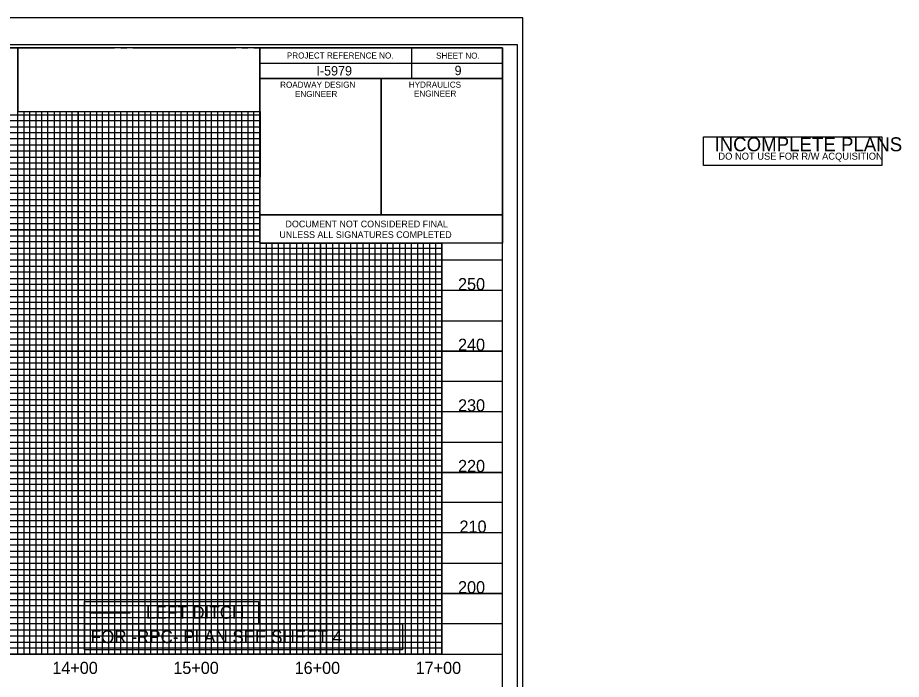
# Model space of a CAD drawing. Extents: x 1810963 to 1812960, y 722070 to 723170.
# Drawn here: x 1812230 to 1812960, y 722624 to 723170 of the extents above; entities that cross this region are included whole.
import ezdxf

# ---------------------------------------------------------------- set-up
doc = ezdxf.new("R2010")
doc.units = 0
for name, color, linetype in [('Exist Horizontal Alignment Tick Label', 7, 'Continuous'), ('Old_Level_11', 7, 'Continuous'), ('Old_Level_2', 7, 'Continuous'), ('Prop Conc 2ft 6in Curb and Gutter', 7, 'Continuous'), ('Prop Dimension Text', 7, 'Continuous'), ('Prop Grid Mask', 7, 'Continuous'), ('Prop Horizontal Alignment Station Label', 7, 'Continuous'), ('Prop RDY Traffic Signal CELL', 7, 'Continuous'), ('Prop Shade Heavy', 7, 'Continuous'), ('Prop Shade Light', 7, 'Continuous'), ('Prop Vertical Profile Ditch Grade Left', 7, 'Continuous'), ('Scratch_Level_0', 7, 'Continuous'), ('Scratch_Level_3', 7, 'Continuous'), ('Sheet Block Title CELL', 7, 'Continuous'), ('Sheet Layout Profile Border Port 1', 7, 'Continuous'), ('Sheet North Arrow CELL', 7, 'Continuous'), ('Sheet Symbology CELL', 7, 'Continuous'), ('Sheet Title CELL', 7, 'Continuous')]:
    doc.layers.add(name, color=color, linetype=linetype)

msp = doc.modelspace()

# ---------------------------------------------------------------- linework, layer by layer
at = {"layer": 'Old_Level_11'}
msp.add_lwpolyline([(1810976.46, 722092.33), (1812642.96, 722092.33), (1812642.96, 723147.43), (1810976.46, 723147.43)], close=True, dxfattribs=at)
at = {"layer": 'Old_Level_2'}
for points in [[(1812285.68, 722688.37), (1812429.34, 722688.37), (1812429.34, 722669.88), (1812285.68, 722669.88)], [(1812285.68, 722669.88), (1812547.95, 722669.88), (1812547.95, 722648.36), (1812285.68, 722648.36)]]:
    msp.add_lwpolyline(points, close=True, dxfattribs=at)
at = {"layer": 'Prop Conc 2ft 6in Curb and Gutter'}
for p, q in [((1812230.46, 722644.88), (1812230.46, 723144.88)), ((1812280.46, 722644.88), (1812280.46, 723092.45)), ((1812330.46, 722644.88), (1812330.46, 723092.45)), ((1812380.46, 722644.88), (1812380.46, 723092.45)), ((1812430.41, 723044.88), (1811130.46, 723044.88)), ((1812430.46, 722644.88), (1812430.46, 723007.33)), ((1812430.46, 722994.88), (1811130.46, 722994.88)), ((1812480.46, 722644.88), (1812480.46, 722983.83)), ((1812530.46, 722644.88), (1812530.46, 722983.83)), ((1812580.46, 722644.88), (1812580.46, 722983.83)), ((1812630.46, 722944.88), (1811130.46, 722944.88)), ((1812630.46, 722894.88), (1811130.46, 722894.88)), ((1812630.46, 722844.88), (1811130.46, 722844.88)), ((1812630.46, 722794.88), (1811130.46, 722794.88)), ((1812630.46, 722744.88), (1811130.46, 722744.88)), ((1812630.46, 722694.88), (1811130.46, 722694.88))]:
    msp.add_line(p, q, dxfattribs=at)
at = {"layer": 'Prop Dimension Text'}
for p, q in [((1812430.41, 722983.83), (1812430.41, 723007.33)), ((1812430.41, 723007.33), (1812630.45, 723007.33)), ((1812430.41, 722983.83), (1812430.41, 723007.33)), ((1812430.41, 723007.33), (1812630.45, 723007.33)), ((1812630.45, 723007.32), (1812630.45, 722983.82)), ((1812630.45, 723007.32), (1812630.45, 722983.82)), ((1812630.45, 722983.83), (1812430.41, 722983.83)), ((1812630.45, 722983.83), (1812430.41, 722983.83))]:
    msp.add_line(p, q, dxfattribs=at)
at = {"layer": 'Prop Horizontal Alignment Station Label'}
msp.add_lwpolyline([(1812796.56, 723048.01), (1812796.56, 723071.51), (1812943.56, 723071.51), (1812943.56, 723048.01)], close=True, dxfattribs=at)
at = {"layer": 'Prop RDY Traffic Signal CELL'}
msp.add_line((1812647.46, 723169.88), (1810963.46, 723169.88), dxfattribs=at)
at = {"layer": 'Prop Shade Heavy'}
for points in [[(1812180.46, 722644.88), (1812230.46, 722644.88), (1812230.46, 723144.88), (1812280.46, 723144.88)], [(1812330.46, 723144.88), (1812380.46, 723144.88)], [(1812380.46, 723092.45), (1812380.46, 722644.88), (1812430.46, 722644.88), (1812430.46, 723144.88), (1812456.76, 723144.88)], [(1812280.46, 723092.45), (1812280.46, 722644.88), (1812330.46, 722644.88), (1812330.46, 723092.45)], [(1812430.46, 723044.88), (1811130.46, 723044.88), (1811130.46, 722994.88), (1812430.46, 722994.88)], [(1812580.46, 722983.83), (1812580.46, 722644.88), (1812630.46, 722644.88), (1812630.46, 722994.88)], [(1812480.46, 722983.83), (1812480.46, 722644.88), (1812530.46, 722644.88), (1812530.46, 722644.88), (1812530.46, 722983.83)], [(1812630.46, 722944.88), (1811130.46, 722944.88), (1811130.46, 722894.88), (1812630.46, 722894.88)], [(1812630.46, 722844.88), (1811130.46, 722844.88), (1811130.46, 722794.88), (1812630.46, 722794.88)], [(1812630.46, 722744.88), (1811130.46, 722744.88), (1811130.46, 722744.88), (1811130.46, 722694.88), (1812630.46, 722694.88)]]:
    msp.add_lwpolyline(points, dxfattribs=at)
at = {"layer": 'Prop Shade Light'}
for p, q in [((1812255.46, 723144.88), (1812305.46, 723144.88)), ((1812355.46, 723144.88), (1812405.46, 723144.88)), ((1812255.46, 722644.88), (1812255.46, 723092.45)), ((1812305.46, 723092.45), (1812305.46, 722644.88)), ((1812355.46, 722644.88), (1812355.46, 723092.45)), ((1812405.46, 723092.45), (1812405.46, 722644.88)), ((1812455.46, 722644.88), (1812455.46, 722983.83)), ((1812205.46, 722644.88), (1812255.46, 722644.88)), ((1812305.46, 722644.88), (1812355.46, 722644.88)), ((1812405.46, 722644.88), (1812455.46, 722644.88))]:
    msp.add_line(p, q, dxfattribs=at)
for points in [[(1812430.46, 723069.88), (1811130.46, 723069.88), (1811130.46, 723019.88), (1812430.46, 723019.88)], [(1812455.46, 722907.68), (1812455.46, 722644.88), (1812505.46, 722644.88), (1812505.46, 722983.83)], [(1812505.46, 722907.68), (1812505.46, 722644.88), (1812555.46, 722644.88), (1812555.46, 722983.83)], [(1812630.46, 722969.88), (1811130.46, 722969.88), (1811130.46, 722919.88), (1812455.46, 722919.88)], [(1812455.46, 722919.88), (1812630.46, 722919.88)], [(1812630.46, 722869.88), (1811130.46, 722869.88), (1811130.46, 722819.88), (1812630.46, 722819.88)], [(1812630.46, 722769.88), (1811130.46, 722769.88), (1811130.46, 722719.88), (1812630.46, 722719.88)], [(1812630.46, 722669.88), (1811130.46, 722669.88)]]:
    msp.add_lwpolyline(points, dxfattribs=at)
at = {"layer": 'Prop Vertical Profile Ditch Grade Left'}
msp.add_line((1812289.59, 722679.06), (1812323.23, 722679.06), dxfattribs=at)
at = {"layer": 'Scratch_Level_3'}
msp.add_lwpolyline([(1811180.46, 723144.88), (1812230.46, 723144.88), (1812230.46, 723092.45), (1812430.5, 723092.45), (1812430.41, 722983.83), (1812580.46, 722983.83), (1812580.46, 722644.88), (1811180.46, 722644.88)], close=True, dxfattribs=at)
at = {"layer": 'Sheet Layout Profile Border Port 1'}
msp.add_lwpolyline([(1811180.46, 722983.83), (1811180.46, 722644.88), (1812580.46, 722644.88), (1812580.46, 722983.83)], dxfattribs=at)
at = {"layer": 'Sheet North Arrow CELL'}
msp.add_lwpolyline([(1810963.46, 722069.88), (1812647.46, 722069.88), (1812647.46, 723169.88), (1810963.46, 723169.88)], close=True, dxfattribs=at)
at = {"layer": 'Sheet Symbology CELL'}
for p, q in [((1812555.46, 723144.83), (1812555.46, 723119.83)), ((1812430.41, 723132.33), (1812630.46, 723132.33)), ((1812530.46, 723119.83), (1812530.46, 723007.38)), ((1811130.46, 722644.88), (1812630.46, 722644.88))]:
    msp.add_line(p, q, dxfattribs=at)
for points in [[(1812630.46, 723144.88), (1811130.46, 723144.88), (1811130.46, 722094.88), (1812630.46, 722094.88)], [(1812430.41, 723144.88), (1812630.46, 723144.88), (1812630.46, 723119.83), (1812430.41, 723119.83)], [(1812430.41, 723119.83), (1812530.46, 723119.83), (1812530.46, 723007.33), (1812430.41, 723007.33)], [(1812530.46, 723119.83), (1812630.46, 723119.83), (1812630.46, 723007.33), (1812530.46, 723007.33)]]:
    msp.add_lwpolyline(points, close=True, dxfattribs=at)
at = {"layer": 'Sheet Title CELL'}
for p, q in [((1812225.46, 723144.88), (1812235.46, 723144.88)), ((1812240.46, 723144.88), (1812245.46, 723144.88)), ((1812250.46, 723144.88), (1812260.46, 723144.88)), ((1812265.46, 723144.88), (1812270.46, 723144.88)), ((1812275.46, 723144.88), (1812285.46, 723144.88)), ((1812290.46, 723144.88), (1812295.46, 723144.88)), ((1812300.46, 723144.88), (1812310.46, 723144.88)), ((1812315.46, 723144.88), (1812320.46, 723144.88)), ((1811180.46, 723089.88), (1812430.46, 723089.88)), ((1812235.46, 723092.45), (1812235.46, 722644.88)), ((1812240.46, 722644.88), (1812240.46, 723092.45)), ((1812245.46, 723092.45), (1812245.46, 722644.88)), ((1812250.46, 722644.88), (1812250.46, 723092.45)), ((1812260.46, 723092.45), (1812260.46, 722644.88)), ((1812265.46, 722644.88), (1812265.46, 723092.45)), ((1812270.46, 723092.45), (1812270.46, 722644.88)), ((1812275.46, 722644.88), (1812275.46, 723092.45)), ((1812285.46, 723092.45), (1812285.46, 722644.88)), ((1812290.46, 722644.88), (1812290.46, 723092.45)), ((1812295.46, 723092.45), (1812295.46, 722644.88)), ((1812300.46, 722644.88), (1812300.46, 723092.45)), ((1812310.46, 723092.45), (1812310.46, 722644.88)), ((1812315.46, 722644.88), (1812315.46, 723092.45)), ((1812320.46, 723092.45), (1812320.46, 722644.88)), ((1812430.41, 723009.88), (1811180.46, 723009.88)), ((1812430.46, 723004.88), (1811180.46, 723004.88)), ((1812430.46, 722999.88), (1811180.46, 722999.88)), ((1811180.46, 722989.88), (1812430.46, 722989.88)), ((1812430.46, 722984.88), (1811180.46, 722984.88)), ((1811180.46, 722979.88), (1812580.46, 722979.88)), ((1812580.46, 722959.88), (1811180.46, 722959.88)), ((1811180.46, 722954.88), (1812580.46, 722954.88)), ((1812580.46, 722934.88), (1811180.46, 722934.88)), ((1811180.46, 722929.88), (1812580.46, 722929.88)), ((1812580.46, 722909.88), (1811180.46, 722909.88)), ((1811180.46, 722904.88), (1812580.46, 722904.88)), ((1812580.46, 722899.88), (1811180.46, 722899.88)), ((1811180.46, 722889.88), (1812580.46, 722889.88)), ((1812580.46, 722884.88), (1811180.46, 722884.88)), ((1811180.46, 722879.88), (1812580.46, 722879.88)), ((1812580.46, 722874.88), (1811180.46, 722874.88)), ((1811180.46, 722864.88), (1812580.46, 722864.88)), ((1812580.46, 722859.88), (1811180.46, 722859.88)), ((1811180.46, 722854.88), (1812580.46, 722854.88)), ((1812580.46, 722849.88), (1811180.46, 722849.88)), ((1811180.46, 722839.88), (1812580.46, 722839.88)), ((1812580.46, 722834.88), (1811180.46, 722834.88)), ((1811180.46, 722829.88), (1812580.46, 722829.88)), ((1812580.46, 722824.88), (1811180.46, 722824.88)), ((1811180.46, 722814.88), (1812580.46, 722814.88)), ((1812580.46, 722809.88), (1811180.46, 722809.88)), ((1811180.46, 722804.88), (1812580.46, 722804.88)), ((1812580.46, 722799.88), (1811180.46, 722799.88)), ((1811180.46, 722789.88), (1812580.46, 722789.88)), ((1812580.46, 722784.88), (1811180.46, 722784.88)), ((1811180.46, 722779.88), (1812580.46, 722779.88)), ((1812580.46, 722774.88), (1811180.46, 722774.88)), ((1811180.46, 722764.88), (1812580.46, 722764.88)), ((1812580.46, 722759.88), (1811180.46, 722759.88)), ((1812580.46, 722754.88), (1811180.46, 722754.88)), ((1812580.46, 722749.88), (1811180.46, 722749.88)), ((1811180.46, 722739.88), (1812580.46, 722739.88)), ((1812580.46, 722734.88), (1811180.46, 722734.88)), ((1811180.46, 722729.88), (1812580.46, 722729.88)), ((1812580.46, 722724.88), (1811180.46, 722724.88)), ((1811180.46, 722714.88), (1812580.46, 722714.88)), ((1812580.46, 722709.88), (1811180.46, 722709.88)), ((1811180.46, 722704.88), (1812580.46, 722704.88)), ((1812580.46, 722699.88), (1811180.46, 722699.88)), ((1811180.46, 722689.88), (1812580.46, 722689.88)), ((1812580.46, 722684.88), (1811180.46, 722684.88)), ((1811180.46, 722679.88), (1812580.46, 722679.88)), ((1812580.46, 722674.88), (1811180.46, 722674.88)), ((1811180.46, 722664.88), (1812580.46, 722664.88)), ((1812580.46, 722659.88), (1811180.46, 722659.88)), ((1811180.46, 722654.88), (1812580.46, 722654.88)), ((1812235.46, 722644.88), (1812240.46, 722644.88)), ((1812245.46, 722644.88), (1812250.46, 722644.88)), ((1812260.46, 722644.88), (1812265.46, 722644.88)), ((1812270.46, 722644.88), (1812275.46, 722644.88)), ((1812285.46, 722644.88), (1812290.46, 722644.88)), ((1812295.46, 722644.88), (1812300.46, 722644.88)), ((1812310.46, 722644.88), (1812315.46, 722644.88))]:
    msp.add_line(p, q, dxfattribs=at)
for points in [[(1812325.46, 723144.88), (1812335.46, 723144.88)], [(1812340.46, 723144.88), (1812345.46, 723144.88)], [(1812350.46, 723144.88), (1812360.46, 723144.88)], [(1812365.46, 723144.88), (1812370.46, 723144.88)], [(1812375.46, 723144.88), (1812385.46, 723144.88)], [(1812390.46, 723144.88), (1812395.46, 723144.88)], [(1812400.46, 723144.88), (1812410.46, 723144.88)], [(1812415.46, 723144.88), (1812420.46, 723144.88)], [(1812425.46, 723144.88), (1812435.46, 723144.88)], [(1812320.46, 722644.88), (1812325.46, 722644.88), (1812325.46, 723092.45)], [(1812335.46, 723092.45), (1812335.46, 722644.88), (1812340.46, 722644.88), (1812340.46, 723092.45)], [(1812345.46, 723092.45), (1812345.46, 722644.88), (1812350.46, 722644.88), (1812350.46, 723092.45)], [(1812360.46, 723092.45), (1812360.46, 722644.88), (1812365.46, 722644.88), (1812365.46, 723092.45)], [(1812370.46, 723092.45), (1812370.46, 722644.88), (1812375.46, 722644.88), (1812375.46, 723092.45)], [(1812385.46, 723092.45), (1812385.46, 722644.88), (1812390.46, 722644.88), (1812390.46, 723092.45)], [(1812395.46, 723092.45), (1812395.46, 722644.88), (1812400.46, 722644.88), (1812400.46, 723092.45)], [(1812410.46, 723092.45), (1812410.46, 722644.88), (1812415.46, 722644.88), (1812415.46, 723092.45)], [(1812420.46, 723092.45), (1812420.46, 722644.88), (1812425.46, 722644.88), (1812425.46, 723092.45)], [(1812430.46, 723084.88), (1811180.46, 723084.88), (1811180.46, 723079.88), (1812430.46, 723079.88)], [(1812430.46, 723074.88), (1811180.46, 723074.88), (1811180.46, 723064.88), (1812430.46, 723064.88)], [(1812430.46, 723059.88), (1811180.46, 723059.88), (1811180.46, 723054.88), (1812430.46, 723054.88)], [(1812430.46, 723049.88), (1811180.46, 723049.88), (1811180.46, 723039.88), (1812430.46, 723039.88)], [(1812430.46, 723034.78), (1811180.56, 723034.78), (1811180.56, 723029.88), (1812430.46, 723029.88)], [(1812430.46, 723024.88), (1811180.46, 723024.88), (1811180.46, 723014.88), (1812430.46, 723014.88)], [(1812435.46, 722983.83), (1812435.46, 722644.88), (1812440.46, 722644.88), (1812440.46, 722983.83)], [(1812445.46, 722983.83), (1812445.46, 722644.88), (1812450.46, 722644.88), (1812450.46, 722983.83)], [(1812460.46, 722983.83), (1812460.46, 722644.88), (1812460.46, 722644.88), (1812465.46, 722644.88), (1812470.46, 722644.88), (1812470.46, 722983.83)], [(1812465.46, 722983.83), (1812465.46, 722644.88)], [(1812475.45, 722983.83), (1812475.36, 722644.93), (1812480.36, 722644.93), (1812485.46, 722644.88), (1812485.46, 722983.83)], [(1812485.46, 722907.68), (1812485.46, 722644.88), (1812490.46, 722644.88), (1812490.46, 722983.83)], [(1812495.46, 722983.83), (1812495.46, 722644.88), (1812500.46, 722644.88), (1812500.46, 722983.83)], [(1812510.46, 722983.83), (1812510.46, 722644.88), (1812515.46, 722644.88), (1812515.46, 722983.83)], [(1812520.46, 722983.83), (1812520.46, 722644.88), (1812525.46, 722644.88), (1812525.46, 722983.83)], [(1812535.46, 722983.83), (1812535.46, 722644.88), (1812540.46, 722644.88), (1812540.46, 722983.83)], [(1812545.46, 722983.83), (1812545.46, 722644.88), (1812550.46, 722644.88), (1812550.46, 722983.83)], [(1812560.46, 722983.83), (1812560.46, 722644.88), (1812565.46, 722644.88), (1812565.46, 722983.83)], [(1812570.46, 722983.83), (1812570.46, 722644.88), (1812575.46, 722644.88), (1812575.46, 722983.83)], [(1812580.46, 722974.88), (1811180.46, 722974.88), (1811180.46, 722964.88), (1812580.46, 722964.88)], [(1812580.46, 722949.88), (1811180.46, 722949.88), (1811180.46, 722939.88), (1812580.46, 722939.88)], [(1812580.46, 722924.88), (1811180.46, 722924.88), (1811180.46, 722914.88), (1812580.46, 722914.88)], [(1812580.46, 722649.88), (1811180.46, 722649.88)]]:
    msp.add_lwpolyline(points, dxfattribs=at)

# ---------------------------------------------------------------- texts
at = {"layer": 'Exist Horizontal Alignment Tick Label'}
for s, p in [('LEFT DITCH', (1812336.41, 722674.13)), ('FOR -RPC- PLAN SEE SHEET 4', (1812290.65, 722654.07))]:
    msp.add_text(s, height=10.5, rotation=360, dxfattribs=at).set_placement(p)
at = {"layer": 'Prop Dimension Text'}
for s, p in [('DOCUMENT NOT CONSIDERED FINAL', (1812451.48, 722996.99)), ('DOCUMENT NOT CONSIDERED FINAL', (1812451.48, 722996.99)), ('UNLESS ALL SIGNATURES COMPLETED', (1812446.41, 722988.19)), ('UNLESS ALL SIGNATURES COMPLETED', (1812446.41, 722988.19))]:
    msp.add_text(s, height=5.5, dxfattribs=at).set_placement(p)
at = {"layer": 'Prop Grid Mask'}
for s, p in [('I-5979', (1812476.99, 723122.19)), ('9', (1812591.02, 723122.49))]:
    msp.add_text(s, height=7.75, dxfattribs=at).set_placement(p)
at = {"layer": 'Prop Horizontal Alignment Station Label'}
for s, height, p in [('INCOMPLETE PLANS', 11.52, (1812805.51, 723059.71)), ('DO NOT USE FOR R/W ACQUISITION', 5.76, (1812808.76, 723052.76))]:
    msp.add_text(s, height=height, dxfattribs=at).set_placement(p)
at = {"layer": 'Scratch_Level_0'}
for s, p in [('250', (1812593.89, 722945.13)), ('240', (1812593.89, 722895.13)), ('230', (1812593.89, 722845.13)), ('220', (1812593.89, 722795.13)), ('210', (1812595.09, 722745.13)), ('200', (1812593.89, 722695.13))]:
    msp.add_text(s, height=10, dxfattribs=at).set_placement(p)
at = {"layer": 'Sheet Block Title CELL'}
for s, p in [('14+00', (1812259.01, 722628.6)), ('15+00', (1812358.88, 722628.6)), ('16+00', (1812459.01, 722628.6)), ('17+00', (1812558.88, 722628.6))]:
    msp.add_text(s, height=10, dxfattribs=at).set_placement(p)
at = {"layer": 'Sheet Symbology CELL'}
for s, height, p in [('PROJECT REFERENCE NO.', 5.0001, (1812452.62, 723136.19)), ('SHEET NO.', 5, (1812575.77, 723136.09)), ('HYDRAULICS', 5, (1812553.27, 723112.14)), ('ROADWAY DESIGN', 5.0001, (1812447.07, 723112.09)), ('ENGINEER', 5, (1812459.32, 723104.49)), ('ENGINEER', 5, (1812557.52, 723104.79))]:
    msp.add_text(s, height=height, dxfattribs=at).set_placement(p)

doc.saveas('drawing.dxf')
